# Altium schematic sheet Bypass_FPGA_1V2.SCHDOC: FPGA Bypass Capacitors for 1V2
size A4; Organization: Altium Limited.; Address1: Level 3, 12a Rodborough Rd; Address2: Frenchs Forest 2086; Address3: NSW; Address4: AUSTRALIA; DocumentNumber: 5; SheetNumber: 5; SheetTotal: 23
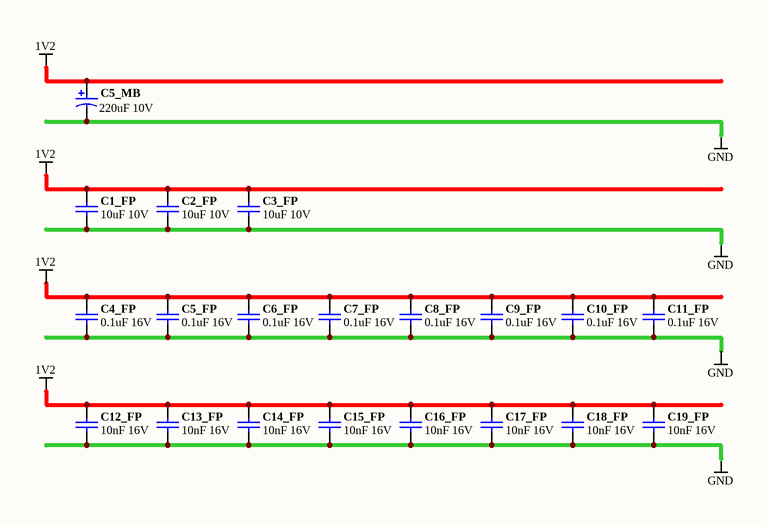
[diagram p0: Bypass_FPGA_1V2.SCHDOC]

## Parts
C1_FP  10uF 10V  [CAPC2012-STAR]
C2_FP  10uF 10V  [CAPC2012-STAR]
C3_FP  10uF 10V  [CAPC2012-STAR]
C4_FP  0.1uF 16V  [CAPC1005-STAR]
C5_FP  0.1uF 16V  [CAPC1005-STAR]
C5_MB  220uF 10V  [CAPC7343-STAR]
C6_FP  0.1uF 16V  [CAPC1005-STAR]
C7_FP  0.1uF 16V  [CAPC1005-STAR]
C8_FP  0.1uF 16V  [CAPC1005-STAR]
C9_FP  0.1uF 16V  [CAPC1005-STAR]
C10_FP  0.1uF 16V  [CAPC1005-STAR]
C11_FP  0.1uF 16V  [CAPC1005-STAR]
C12_FP  10nF 16V  [CAPC1005-STAR]
C13_FP  10nF 16V  [CAPC1005-STAR]
C14_FP  10nF 16V  [CAPC1005-STAR]
C15_FP  10nF 16V  [CAPC1005-STAR]
C16_FP  10nF 16V  [CAPC1005-STAR]
C17_FP  10nF 16V  [CAPC1005-STAR]
C18_FP  10nF 16V  [CAPC1005-STAR]
C19_FP  10nF 16V  [CAPC1005-STAR]

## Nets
1V2: C1_FP.1 C2_FP.1 C3_FP.1 C4_FP.1 C5_FP.1 C5_MB.1 C6_FP.1 C7_FP.1 C8_FP.1 C9_FP.1 C10_FP.1 C11_FP.1 C12_FP.1 C13_FP.1 C14_FP.1 C15_FP.1 C16_FP.1 C17_FP.1 C18_FP.1 C19_FP.1
GND: C1_FP.2 C2_FP.2 C3_FP.2 C4_FP.2 C5_FP.2 C5_MB.2 C6_FP.2 C7_FP.2 C8_FP.2 C9_FP.2 C10_FP.2 C11_FP.2 C12_FP.2 C13_FP.2 C14_FP.2 C15_FP.2 C16_FP.2 C17_FP.2 C18_FP.2 C19_FP.2

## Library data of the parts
C1_FP C2_FP C3_FP = D-101-0087: Capacitor, Ceramic, 10uF 10% 10V 0805 (2012) X5R; Polarity: Non-Polarized
C4_FP C5_FP C6_FP C7_FP C8_FP C9_FP C10_FP C11_FP = D-101-0080: Capacitor, Ceramic, 0.1uF 10% 16V 0402 (1005) X7R; Polarity: Non-Polarized
C5_MB = D-101-0088: Capacitor, Tantalum, 220uF 10% 10V MCCT-D (7343-31); Polarity: Polarized
C12_FP C13_FP C14_FP C15_FP C16_FP C17_FP C18_FP C19_FP = D-101-0077: Capacitor, Ceramic, 10nF 10% 16V 0402 (1005) X7R; Polarity: Non-Polarized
